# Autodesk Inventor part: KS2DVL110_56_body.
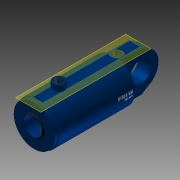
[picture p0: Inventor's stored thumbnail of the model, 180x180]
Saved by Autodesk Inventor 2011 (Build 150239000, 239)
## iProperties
Created: 2010-10
Document SubType Name: Modeling
Designer: TB
Mass: 405.061 g
Surface Area: 916.939 cm^2
Volume: 405.061 cm^3
Density: 1 g/cm^3
Author: TB
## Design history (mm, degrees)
sketch "Sketch2"
  geometry: L1 (-35, -3)-(-35, 3); L2 (-35, -9)-(-35, 9); L3 (-35, 0)-(-35, 65); L4 (-35, 65)-(-266, 65); L5 (-266, 65)-(-266, 62.5); L6 (-266, 62.5)-(-278, 62.5); L7 (-278, 62.5)-(-278, 32); L8 (-278, 32)-(-281, 29); L9 (-281, 29)-(-281, 28); L10 (-281, 28)-(-198, 28); L11 (-198, 28)-(-198, 55); L12 (-198, 55)-(-58, 55); L13 (-58, 55)-(-58, 0); L14 (-58, 0)-(-35, 0); L15 (-58, 0)-(-148.421, 0); L16 (-35, 9)-(-32, 12) reference; L17 (-32, 12)-(-35, 12) reference; L18 (-35, 12)-(-35, 9) reference; L19 (-32, 12)-(-35, 9) reference; L20 (-32, 12)-(-35, 12) reference; L21 (-35, 9)-(-35, 12) reference; L22 (-35, 9)-(-32, 12) reference; 1 further point
  constraints: 44 end point, 8 perpendicular, 6 parallel, 5 collinear, 2 horizontal, 2 vertical, 1 coincident, 1 midpoint, 1 point on line, 10 other
  dimensions: "DiaY" = 130 diameter of L4 L15; "DiaI" = 110 diameter of L12 L15; "d4" = 1 distance of L8.end L9.end; "d5" = 45 deg angle of L10 L8; "d6" = 3 distance between parallel lines of L7 L9; "DiaStang" = 56 diameter of L10 L15; "RindDia" = 125 diameter of L6 L15; "RingLengde" = 12 distance of L5.end L6.end; "RingTykk" = 80 distance between parallel lines of L11 L7; "KroppLengde" = 243 distance between parallel lines of L7 L3 (derived); "BunnTykkelse" = 23 distance between parallel lines of L13 L3
revolve "Kropp" sketch "Sketch2" stored, may be unused: angle "d13" = 90 deg
sketch "Sketch3"
  geometry: L1 (-58, -55)-(-58, 55) reference; L2 (-58, 0.01)-(-158, 0.01); L3 (-158, -0.01)-(-58, -0.01); A1 r 0.01 centre (-158, 0) between (-158, 0.01) and (-158, -0.01); A2 r 0.01 centre (-58, 0) between (-58, -0.01) and (-58, 0.01); 2 further points
  constraints: 4 end point, 4 point on circle, 4 tangent, 2 centre point, 1 coincident, 1 midpoint, 1 parallel, 1 perpendicular
  dimensions: "d17" = 0.01 radius of A2; "d18" = 100 distance of L2.start L2.end (= Slaglengde)
feature "BaneTransitionalConstraint" sketch "Sketch3" dims "d19" = 2, "d20" = 0
sketch "Sketch6"
  geometry: L1 (-91, 0)-(91, 0) reference; L2 (13.883, 63.5)-(-11.843, 63.5); L3 (65, 0)-(65, 31.248); L4 (-65, 0)-(-65, -18.451); A1 r 65 centre (0, 0) between (-65, 0) and (65, 0) reference; 2 further points
  constraints: 6 end point, 2 point on circle, 2 vertical, 2 other
  dimensions: "d30" = 63.5 distance from line of point (0, 0) L2 (computed from DiaY); "d31" = 0 deg angle of L1 L2 (computed from Vinkel_Plussport); "d37" = 90 deg angle of L2 L3; "d38" = 90 deg angle of L2 L4
  node "Projected Loop3"
workplane "Work Plane5"
sketch "Sketch7"
  geometry: L1 (13.883, -337.2)-(13.883, 56.2) reference; L2 (-19.633, -35)-(38.367, -35) reference; C1 r 17.5 at (13.883, -52.5); 1 further point
  constraints: 1 centre point, 1 point on line
  dimensions: "PortDia" = 35 diameter of C1
extrude "Extrusion2" cut sketch "Sketch7" stored distance "d34" = 1.5; taper "d35" = 0 deg
workplane "Work Plane7"
sketch "Sketch4"
  geometry: L1 (-16.68, -40)-(-16.68, -78.777); L2 (-16.68, -78.777)-(16.68, -78.777); L3 (16.68, -78.777)-(16.68, -40); L4 (16.68, -40)-(-16.68, -40); L5 (-40.643, -40)-(0, -40); L6 (-29, -35)-(29, -35); L7 (0, -35)-(0, -40); 2 further points
  constraints: 6 end point, 2 midpoint, 2 other
  dimensions: "d40" = 5 distance of L7.start L5.end
emboss "Emboss1" sketch "Sketch4" dims "d4" = 1, "d5" = 45 deg, "d6" = 3, "d22" = 0.2, "d23" = 0, "DiaI" = 110, "DiaY" = 130, "RindDia" = 125, "DiaStang" = 56, "RingTykk" = 80, "RingLengde" = 12, "KroppLengde" = 243 (derived), "BunnTykkelse" = 23
workplane "Work Plane8"
sketch "Sketch8"
  geometry: L1 (-29, -35)-(29, -35); L2 (0, -35)-(0, -40); L3 (-5.906, -110.587)-(-5.906, -40); L4 (-5.906, -40)-(5.906, -40); L5 (5.906, -40)-(5.906, -110.587); L6 (5.906, -110.587)-(-5.906, -110.587); L7 (65, -35)-(-65, -35); L8 (65, -35)-(-65, -35) reference; 3 further points
  constraints: 6 end point, 4 midpoint, 2 other
  dimensions: "d42" = 5 distance of L2.start L2.end
emboss "Emboss2" sketch "Sketch8" dims "d4" = 1, "d5" = 45 deg, "d6" = 3, "d43" = 0.2, "d44" = 0, "DiaI" = 110, "DiaY" = 130, "RindDia" = 125, "DiaStang" = 56, "RingTykk" = 80, "RingLengde" = 12, "KroppLengde" = 243 (derived), "BunnTykkelse" = 23
sketch "Sketch9"
  geometry: A1 r 12.5 centre (9.367, -52.5) between (0, -60.776) and (18.735, -60.776) reference; 1 further point
hole "Hole1" sketch "Sketch9" at (9.367, -52.5) diameter "d45" = 14.95; stored, may be unused: countersink angle "d49" = 82 deg, drill point angle "d51" = 118 deg; dims "d46" = 6, "d47" = 3.023, "d48" = 2, "DiaInvPluss" = 24.5
workplane "Work Plane9"
sketch "Sketch10"
  geometry: L1 (-91, 0)-(91, 0) reference; L2 (0, 65)-(13.136, 65); L3 (0, 65)-(0, 31.79); L4 (17.5, 62.6)-(17.5, 82.5); L5 (17.5, 82.5)-(0, 82.5); L6 (0, 82.5)-(0, 65); L7 (0, 65)-(17.5, 62.6); C1 r 65 at (0, 0) reference; A1 r 65 centre (0, 0) between (0, 65) and (17.5, 62.6); 1 further point
  constraints: 12 end point, 4 perpendicular, 2 concentric, 2 point on circle, 1 centre point, 1 point on line, 1 tangent
  dimensions: "d53" = 0 deg angle of L1 L2 (computed from Vinkel_Minusport); "DiaUtvStussMinus" = 35 diameter of L4 L3; "HøydeStussMinuss" = 17.5 distance between parallel lines of L2 L5
revolve "Revolution2" sketch "Sketch10" stored, may be unused: angle "d56" = 90 deg
hole "Hole2" diameter "d59" = 24.117; stored, may be unused: countersink angle "d63" = 82 deg, drill point angle "d65" = 118 deg; dims "d57" = 10, "d58" = 10, "d60" = 6, "d61" = 3.023, "d62" = 2, "DiaInvStussMinus" = 24.5
fillet "Fillet1" dims "d66" = 2
sketch "Sketch15"
  geometry: L1 (20, -61.847)-(20, 61.847); L2 (-20, -61.847)-(-20, 61.847); L3 (0, 91)-(0, -91) reference; A1 r 65 centre (0, 0) between (20, -61.847) and (-20, -61.847) reference; A2 r 65 centre (0, 0) between (20, 61.847) and (-20, 61.847); A3 r 65 centre (0, 0) between (-20, -61.847) and (20, -61.847)
  constraints: 8 point on circle, 4 end point, 4 point on line, 2 centre point, 2 concentric, 2 parallel, 1 coincident
  dimensions: "EyeBunnTykk" = 20 distance from line of L1 A1.centre; "EyeBunnTykk2" = 20 distance from line of A1.centre L2
extrude "Extrusion6" join sketch "Sketch15" taper "d98" = 0 deg; distance "LengdeEyeMinussBunntykk" = 116
sketch "Sketch16"
  geometry: L1 (-266, 65)-(81, 65) reference; L2 (-266, -65)-(81, -65) reference; L3 (-266, 65)-(81, 65) reference; L4 (81, 65)-(81, 61.847) reference; L5 (81, -61.847)-(81, 61.847) reference; L6 (-337.761, 0)-(164.566, 0) reference; L7 (24, 65)-(81, 65); L8 (81, 65)-(81, 8); A1 r 57 centre (24, 8) between (81, 8) and (24, 65); 6 further points; 2 other entities
  constraints: 4 end point, 4 tangent, 2 point on circle, 2 point on line, 1 centre point, 1 collinear, 1 perpendicular, 2 other
  dimensions: "d137" = 8 distance from line of L8.end L6
extrude "Extrusion7" cut sketch "Sketch16" taper "d102" = 0 deg; stored distance "ExtruEyeBunn" = 40
mirror "Mirror1"
sketch "Sketch20"
  geometry: L1 (-266, 65)-(81, 65) reference; L2 (81, -61.847)-(81, 61.847) reference; L3 (81, 65)-(81, 61.847) reference; L4 (-336.202, 0)-(155.214, 0) reference; L5 (-35, -61.847)-(-35, 61.847) reference; L6 (-35, 0)-(28, 0); L7 (28, 0)-(28, 20.918); L8 (54.968, 46.709)-(30.665, 60.74); A1 r 53.935 centre (28, 0) between (81, 10) and (54.968, 46.709); A2 r 30 centre (15.161, 35.057) between (30.665, 60.74) and (17.01, 65); 1 further point
  constraints: 6 end point, 4 point on circle, 3 point on line, 2 centre point, 1 coincident, 1 midpoint, 1 perpendicular, 1 tangent
  dimensions: "d147" = 63 distance of L6.start L6.end; "d157" = 10 distance from line of L4 A1.start; "d158" = 30 deg angle of L1 L8; "d159" = 30 radius of A2
extrude "Extrusion10" cut sketch "Sketch20" stored distance "d144" = 10; taper "d145" = 0 deg
mirror "Mirror2"
sketch "Sketch17"
  geometry: L1 (123.693, 0)-(0, 0) reference; L2 (61.847, -318.4)-(61.847, 188.4) reference; C1 r 32 at (61.847, 63); 1 further point
  constraints: 1 centre point, 1 point on line
  dimensions: "DiaHullEyeBunn" = 64 diameter of C1; "d125" = 63 distance from line of C1.centre L1
extrude "Extrusion8" cut sketch "Sketch17" taper "d105" = 0 deg; distance "ExtruHullEye" = 40
pattern_circular "Circular Pattern1 Only Subsea" dims "d108" = 180 deg (derived)
workplane "Work Plane11"
sketch "Sketch18"
  geometry: L1 (0, -69.6)-(0, 11.6) reference; L2 (55, -58)-(-55, -58) reference; L3 (55, -58)-(-55, -58) reference; C1 r 17.5 at (0, -26); 1 further point
  constraints: 1 centre point
  dimensions: "DiaForsenkPlussPort" = 35 diameter of C1; "PlassPlussport" = 32 distance from line of L2 C1.centre
extrude "Extrusion9" cut sketch "Sketch18" stored distance "d113" = 10; taper "d114" = 0 deg
sketch "Sketch19"
  geometry: 10 further points
  constraints: 1 other
hole "Hole3" sketch "Sketch19" at (0, -26) diameter "d115" = 24.117; stored, may be unused: countersink angle "d119" = 90 deg, drill point angle "d121" = 118 deg; dims "d116" = 6, "d117" = 4, "d118" = 2, "d120" = 14.5
pattern_circular "Circular Pattern2 Only Subsea" dims angle "d123" = 360 deg
body "Solid1"
chamfer "Chamfer" distance "Chamfer" = 1; stored, may be unused: second distance "d15" = 2, angle "d16" = 45 deg
node "Projected Loop2"
body "Srf1"
node "Projected Loop10"
other parameters: "Slaglengde" = 100, "Forlengelse_rør" = 0, "Vinkel_Plussport" = 0 [user parameter; used in 1 equation term], "Vinkel_Minusport" = 0, "d32" = 90 deg, "d39" = 90 deg, "d41" = 90 deg, "PortMinusPlass" = -76, "Minusport2" = 180 deg, "ForsenkningPlussPort" = 63.2 (derived)
